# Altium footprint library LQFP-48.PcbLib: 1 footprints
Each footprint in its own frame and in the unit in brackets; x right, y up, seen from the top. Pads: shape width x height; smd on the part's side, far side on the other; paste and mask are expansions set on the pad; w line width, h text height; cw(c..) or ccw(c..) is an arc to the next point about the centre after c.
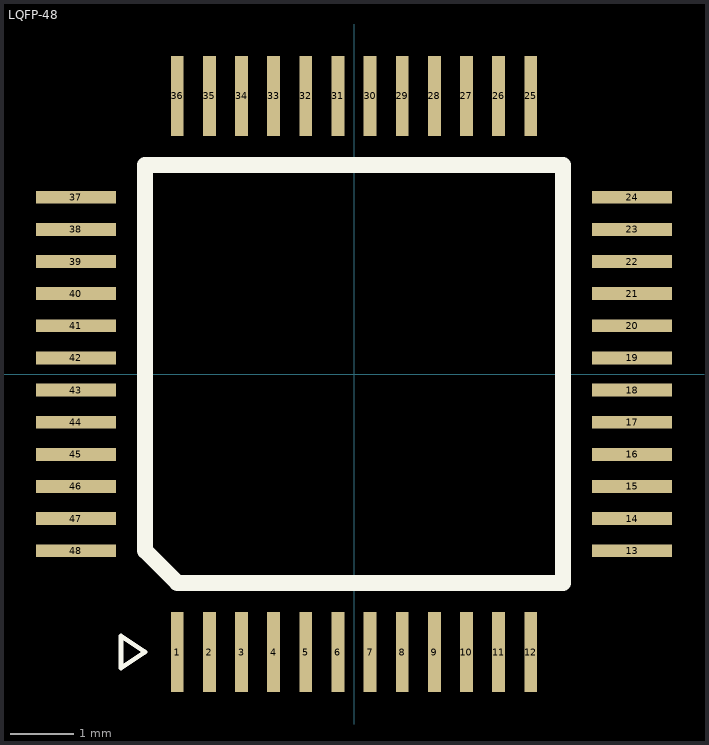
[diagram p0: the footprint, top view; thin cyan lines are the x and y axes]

## LQFP-48 [mil] "VS1003   7*7*1.4mm"
pads (48):
  rect 8x50 smd: 1(-110,-173) 2(-90,-173) 3(-70,-173) 4(-50,-173) 5(-30,-173) 6(-10,-173) 7(10,-173) 8(30,-173) 9(50,-173) 10(70,-173) 11(90,-173) 12(110,-173) 25(110,173) 26(90,173) 27(70,173) 28(50,173) 29(30,173) 30(10,173) 31(-10,173) 32(-30,173) 33(-50,173) 34(-70,173) 35(-90,173) 36(-110,173)
  rect 50x8 smd: 13(173,-110) 14(173,-90) 15(173,-70) 16(173,-50) 17(173,-30) 18(173,-10) 19(173,10) 20(173,30) 21(173,50) 22(173,70) 23(173,90) 24(173,110) 37(-173,110) 38(-173,90) 39(-173,70) 40(-173,50) 41(-173,30) 42(-173,10) 43(-173,-10) 44(-173,-30) 45(-173,-50) 46(-173,-70) 47(-173,-90) 48(-173,-110)
Top Overlay:
  lines w3: -145,-183 -130,-173 -145,-163 -145,-183
  lines w10: -130,-110 -130,130 130,130 130,-130 -110,-130 -130,-110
